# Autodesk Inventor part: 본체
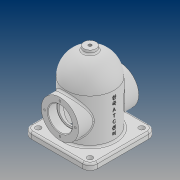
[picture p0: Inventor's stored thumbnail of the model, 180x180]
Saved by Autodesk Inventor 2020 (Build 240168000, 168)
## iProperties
Created: 2021-08
Part Number: 본체
Material: 일반
Document SubType Name: Modeling
Designer: PC312-
Density: 1 g/cm^3
Appearance: 기본값
Author: PC312-
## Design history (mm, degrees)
sketch "스케치4"
  geometry: L1 (0, 0)-(124, 0); L2 (84, -40)-(0, -40); L3 (0, -40)-(0, 0); A1 r 40 centre (84, 0) between (84, -40) and (124, 0)
  constraints: 6 end point, 2 horizontal, 2 point on circle, 1 centre point, 1 horizontal alignment, 1 tangent, 1 vertical, 1 vertical alignment
  dimensions: "d5" = 124 distance of L1.end L1.start; "d6" = 80 diameter of A1
revolve "회전1" sketch "스케치4" stored, may be unused: angle "d7" = 90 deg
feature "쉘1" dims "d8" = 8
sketch "스케치5"
  geometry: L1 (-55, 55)-(55, 55); L2 (55, 55)-(55, -55); L3 (55, -55)-(-55, -55); L4 (-55, -55)-(-55, 55); L5 (-55, 55)-(55, -55); L6 (55, 55)-(-55, -55); C1 r 32 at (0, 0) reference; 1 further point
  constraints: 12 end point, 2 midpoint, 2 parallel, 1 horizontal, 1 perpendicular
  dimensions: "d9" = 110 distance of L1.end L2.end; "d10" = 110 distance of L2.end L3.end
extrude "돌출2" join sketch "스케치5" distance "d11" = 10; taper "d12" = 0 deg
node "작업 평면1"
sketch "스케치6"
  geometry: L1 (55, 0)-(-55, 0) reference; C1 r 31 at (0, 48); 2 further points
  constraints: 1 centre point, 1 midpoint, 1 vertical alignment
  dimensions: "d14" = 62 diameter of C1; "d15" = 48 distance from line of L1 C1.centre
extrude "돌출3" join sketch "스케치6" stored distance "d16" = 10; taper "d17" = 0 deg
sketch "스케치7"
  geometry: L1 (55, -48)-(-55, -48) reference; C1 r 20 at (0, 0); C2 r 31 at (0, 0) reference; 2 further points
  constraints: 1 centre point, 1 concentric, 1 midpoint, 1 vertical alignment
  dimensions: "d18" = 40 diameter of C1
extrude "돌출4" cut sketch "스케치7" distance "d19" = 15; taper "d20" = 0 deg
sketch "스케치9"
  geometry: C1 r 16.5 at (0, 0); C2 r 20 at (0, 0) reference; 1 further point
  constraints: 1 centre point, 1 concentric
  dimensions: "d21" = 33 diameter of C1
extrude "돌출5" cut sketch "스케치9" extent not by distance; stored distance "d22" = 15; taper "d23" = 0 deg
sketch "스케치10"
  geometry: C1 r 31 at (0, 0) reference; 2 further points
  constraints: 1 vertical alignment
  dimensions: "d24" = 25.5 distance of point (0, -25.5) C1.centre
hole "구멍1" sketch "스케치10" at (0, -25.5) diameter "d25" = 3.242; stored, may be unused: countersink angle "d29" = 90 deg, drill point angle "d31" = 118 deg; dims "d26" = 8, "d27" = 4, "d28" = 2, "d30" = 10
sketch "스케치11"
  geometry: L1 (-55, 55)-(-55, -55) reference; L2 (-55, -55)-(55, -55) reference; C1 r 4.5 at (-43, -43); 1 further point
  constraints: 1 centre point
  dimensions: "d35" = 9 diameter of C1; "d36" = 12 distance from line of L1 C1.centre; "d37" = 12 distance from line of L2 C1.centre
extrude "돌출6" cut sketch "스케치11" extent not by distance; stored distance "d38" = 0; taper "d39" = 0 deg
node "작업 평면2"
sketch "스케치12"
  geometry: C1 r 10 at (55, -55); 1 further point
  constraints: 1 centre point, 1 coincident
  dimensions: "d47" = 20 diameter of C1
extrude "돌출7" join sketch "스케치12" stored distance "d48" = 15; taper "d49" = 0 deg
sketch "스케치13"
  geometry: C1 r 10 at (0, 0) reference; 2 further points
  constraints: 1 coincident
hole "구멍2" sketch "스케치13" at (0, 0) diameter "d50" = 5.1881; stored, may be unused: countersink angle "d54" = 90 deg, drill point angle "d56" = 0 deg; dims "d51" = 12, "d52" = 4, "d53" = 2, "d55" = 30
fillet "모깎기1" dims "d57" = 12
chamfer "모따기1" distance "d58" = 1; stored, may be unused: second distance "d59" = 2, angle "d60" = 45 deg
fillet "모깎기2" dims "d61" = 3
fillet "모깎기3" dims "d62" = 3
fillet "모깎기4" dims "d63" = 3
fillet "모깎기5" dims "d64" = 3
node "작업 평면3"
sketch "스케치14" dims "d6" = 80
  geometry: L1 (0, -43)-(0, 43) reference; 3 further points
  constraints: 1 horizontal alignment, 1 midpoint, 1 other
  dimensions: "d66" = 48 distance from line of L1 point (48, 0)
feature "엠보싱1" sketch "스케치14" dims "d67" = 0.5, "d68" = 0
fillet "모깎기6" dims "d69" = 0.3
node "솔리드2"
mirror "미러1"
pattern_circular "원형 패턴1" dims angle "d33" = 360 deg
mirror "미러2"
pattern_linear "직사각형 패턴1" dims "d42" = 86, "d45" = 86
feature "A9D066F2-1C7D-4E18-AEED-F7BC21143FA4" dims "d25" = 3.242, "d26" = 8, "d27" = 4, "d28" = 2, "d29" = 90 deg, "d30" = 10, "d31" = 118 deg
other parameters: "d46" = -129, "d65" = 46.5
